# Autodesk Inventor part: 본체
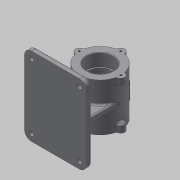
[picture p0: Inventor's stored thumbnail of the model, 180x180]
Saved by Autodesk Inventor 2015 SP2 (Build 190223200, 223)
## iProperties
Created: 2015-12
Part Number: 본체
Material: 일반
Document SubType Name: Modeling
Designer: AMC
Density: 1 g/cm^3
Appearance: 기본값
Author: AMC
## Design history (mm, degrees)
sketch "스케치1"
  geometry: C1 r 37 at (0, 0); 1 further point
  constraints: 1 centre point, 1 coincident
  dimensions: "d0" = 74 diameter of C1
extrude "돌출1" new body sketch "스케치1" distance "d1" = 85; taper "d2" = 0 deg
sketch "스케치2"
  geometry: L1 (-55, -70)-(55, -70); L2 (55, -70)-(55, -80); L3 (55, -80)-(-55, -80); L4 (-55, -80)-(-55, -70); 1 further point
  constraints: 8 end point, 2 parallel, 1 horizontal, 1 perpendicular
  dimensions: "d3" = 10 distance of L3.end L1.start; "d4" = 80 distance from line of L3 point (0, 0); "d5" = 110 distance of L2.end L3.end; "d6" = 55 distance from line of L4 point (0, 0)
extrude "돌출2" join sketch "스케치2" distance "d7" = 37.5; taper "d9" = 0 deg; dims "d8" = 102.5, "d10" = 0
node "작업 평면1"
sketch "스케치3"
  geometry: L1 (122.5, 117)-(107.5, 117); L2 (110.048, 124)-(122.5, 124); L3 (122.5, 124)-(122.5, 117); L4 (122.5, 43)-(122.5, 117) reference; L5 (37.5, 117)-(37.5, 43) reference; L6 (122.5, 43)-(122.5, 117) reference; L7 (122.5, 117)-(37.5, 117) reference; L8 (107.5, 117)-(110.048, 124); 1 further point
  constraints: 8 end point, 1 horizontal, 1 parallel
  dimensions: "d11" = 0 distance between parallel lines of L4 L3; "d12" = 0 distance between parallel lines of L7 L1; "d13" = 7 distance of L2.end L1.start; "d15" = 110 deg angle of L7 L8; "d16" = 15 distance of L1.start L1.end
revolve "회전1" sketch "스케치3" stored, may be unused: angle "d17" = 90 deg
sketch "스케치4"
  geometry: C1 r 21 at (0, 0); 1 further point
  constraints: 1 centre point, 1 coincident
  dimensions: "d21" = 42 diameter of C1
extrude "돌출3" cut sketch "스케치4" distance "d22" = 100; taper "d23" = 0 deg
sketch "스케치5"
  geometry: C1 r 23.5 at (0, 0); 1 further point
  constraints: 1 centre point, 1 coincident
  dimensions: "d24" = 47 diameter of C1
extrude "돌출4" cut sketch "스케치5" distance "d25" = 22; taper "d26" = 0 deg
sketch "스케치6"
  geometry: C1 r 23.5 at (0, 0); 1 further point
  constraints: 1 centre point, 1 coincident
  dimensions: "d27" = 47 diameter of C1
extrude "돌출5" cut sketch "스케치6" distance "d28" = 22; taper "d29" = 0 deg
sketch "스케치8"
  geometry: L1 (92, 84)-(18, 84); L2 (18, 84)-(18, 76); L3 (18, 76)-(92, 76); L4 (92, 76)-(92, 84); L5 (110, 0)-(110, 140) reference; L6 (0, 0)-(110, 0) reference; L7 (0, 0)-(0, 140) reference; L8 (110, 140)-(0, 140) reference; L9 (55, 84)-(55, 76); 1 further point
  constraints: 10 end point, 2 midpoint, 2 parallel, 1 horizontal, 1 perpendicular
  dimensions: "d40" = 8 distance of L3.end L1.start; "d41" = 76 distance between parallel lines of L6 L3; "d42" = 74 distance of L1.start L1.end; "d43" = 55 distance between parallel lines of L5 L9
extrude "돌출6" join sketch "스케치8" stored distance "d44" = 22; taper "d45" = 0 deg
sketch "스케치9"
  geometry: L1 (84, 10)-(84, 80) reference; L2 (84, 80)-(76, 80) reference; L3 (76, 10)-(76, 80) reference; L4 (84, 10)-(76, 10) reference; L5 (84, 10)-(84, 80) reference; L6 (0, 10)-(140, 10) reference; L7 (100.948, 43)-(105, 10); L8 (122.5, 43)-(37.5, 43) reference; 1 further point
  constraints: 2 end point, 2 point on line
  dimensions: "d50" = 97 deg angle of L6 L7; "d51" = 21 distance of L1.start L7.end
feature "리브1" sketch "스케치9" dims "d52" = 1, "d53" = 12, "d54" = 0, "d55" = 0, "d56" = 1, "d57" = 1
sketch "스케치10"
  geometry: L1 (122.5, 43)-(37.5, 43) reference; L2 (76, 10)-(76, 80) reference; L3 (0, 10)-(140, 10) reference; L4 (100.888, 43.49)-(105, 10) reference; L5 (59.052, 43)-(55, 10); 1 further point
  constraints: 2 end point, 2 point on line
  dimensions: "d58" = 97 deg angle of L3 L5; "d59" = 50 distance of L4.end L5.end
feature "리브2" sketch "스케치10" dims "d60" = 1, "d61" = 12, "d62" = 0, "d63" = 0, "d64" = 1, "d65" = 1
sketch "스케치11"
  geometry: L1 (110, 0)-(0, 0) reference; L2 (110, -140)-(110, 0) reference; L3 (0, -140)-(110, -140) reference; L4 (0, -140)-(0, 0) reference; C1 r 4 at (98, -12); 1 further point
  constraints: 1 centre point
  dimensions: "d66" = 8 diameter of C1; "d67" = 12 distance from line of L2 C1.centre; "d68" = 12 distance from line of L1 C1.centre
extrude "돌출7" cut sketch "스케치11" distance "d69" = 22; taper "d70" = 0 deg
fillet "모깎기1" dims "d77" = 12
fillet "모깎기2" dims "d78" = 0.3
chamfer "모따기1" distance "d79" = 1; stored, may be unused: second distance "d80" = 2, angle "d81" = 45 deg
fillet "모깎기4" dims "d83" = 3
fillet "모깎기5" dims "d84" = 3
fillet "모깎기6" dims "d85" = 3
fillet "모깎기7" dims "d86" = 3
fillet "모깎기8" dims "d87" = 3
sketch "스케치12"
  geometry: C1 r 24.5 at (0, 0) reference; A1 r 37 centre (0, 0) between (-9.104, 35.862) and (9.104, 35.863) reference; A2 r 3 centre (9.842, 38.77) between (6.889, 38.239) and (9.104, 35.863) reference; A3 r 7 centre (0, 37) between (6.889, 38.239) and (-6.889, 38.239) reference; A4 r 3 centre (-9.842, 38.77) between (-9.104, 35.862) and (-6.889, 38.239) reference; 2 further points
  constraints: 1 coincident
hole "구멍2" sketch "스케치12" at (0, 37) diameter "d88" = 3.242; stored, may be unused: countersink angle "d92" = 90 deg, drill point angle "d94" = 118 deg; dims "d89" = 9, "d90" = 4, "d91" = 2, "d93" = 11
node "작업 평면3"
node "작업 평면4"
node "작업 평면5"
node "작업 평면6"
sketch "스케치14"
  geometry: L1 (4.819, 28.47)-(4.819, -48.47); L2 (4.819, -48.47)-(-3.851, -48.47); L3 (-3.851, -48.47)-(-3.851, 28.47); L4 (-3.851, 28.47)-(4.819, 28.47); L5 (4.819, -10)-(-3.851, -10); L6 (18.921, 32.5)-(-18.921, 32.5) reference; 1 further point
  constraints: 2 end point, 2 midpoint, 2 other
  dimensions: "d102" = 42.5 distance between parallel lines of L6 L5
feature "엠보싱1" sketch "스케치14" dims "d11" = 0, "d12" = 0, "d13" = 7, "d15" = 110 deg, "d16" = 15, "d103" = 0.5, "d104" = 0
chamfer "모따기2" distance "d105" = 1; stored, may be unused: second distance "d106" = 2, angle "d107" = 45 deg
node "솔리드1"
pattern_linear "직사각형 패턴1" dims "d73" = 116, "d76" = 86
pattern_circular "원형 패턴3" dims "d96" = 360 deg
mirror "대칭3"
node "투영된 루프1"
node "투영된 루프3"
node "투영된 루프4"
node "투영된 루프5"
node "투영된 루프6"
